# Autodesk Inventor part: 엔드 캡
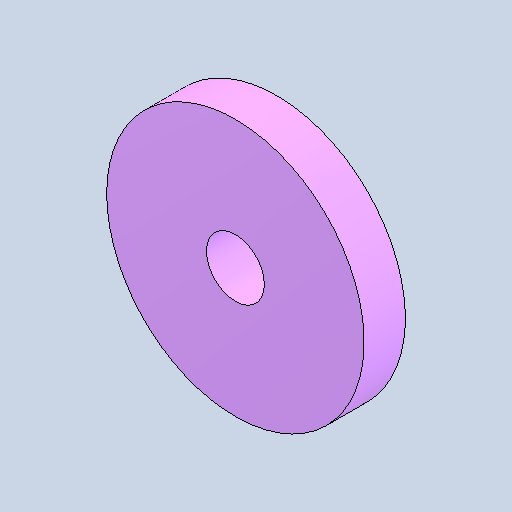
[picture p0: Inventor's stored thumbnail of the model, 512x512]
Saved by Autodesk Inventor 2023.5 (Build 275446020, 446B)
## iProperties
Created: 2026-07
Part Number: 엔드 캡
Material: 강철, 연강
Document SubType Name: Modeling
Designer: 1강의실14
Density: 7.85 g/cm^3
Appearance: 기본값
Author: jhkim
Sending System: Autodesk Inventor 2027
Preprocessor: ST-DEVELOPER v20.1
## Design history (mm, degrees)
node "엔드 캡1"
node "솔리드2"
node "솔리드1"
